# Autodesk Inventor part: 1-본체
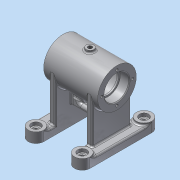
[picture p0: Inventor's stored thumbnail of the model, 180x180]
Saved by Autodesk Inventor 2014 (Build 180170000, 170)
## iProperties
Created: 2015-11
Part Number: 1-본체
Material: 알루미늄 6061
Document SubType Name: Modeling
Designer: 103-21
Mass: 358.521 g
Surface Area: 458.965 cm^2
Volume: 132.296 cm^3
Density: 2.71 g/cm^3
Appearance: 알루미늄 - 평지
Author: 103-21
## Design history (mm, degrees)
sketch "스케치1"
  geometry: L1 (40, -40)-(-40, -40); L2 (-40, -40)-(-40, 40); L3 (-40, 40)-(40, 40); L4 (40, 40)-(40, -40); L5 (40, -40)-(-40, 40); L6 (-40, -40)-(40, 40); L7 (-20, 40)-(-20, -40); L8 (20, 40)-(20, -40); 1 further point
  constraints: 16 end point, 4 point on line, 3 perpendicular, 2 midpoint, 2 parallel, 1 horizontal
  dimensions: "d0" = 20 distance of L7.start L2.end; "d1" = 20 distance of L3.end L8.start; "d2" = 80 distance of L1.end L2.end; "d3" = 80 distance between parallel lines of L4 L2
extrude "돌출1" new body sketch "스케치1" distance "d4" = 10; taper "d5" = 0 deg
sketch "스케치2"
  geometry: L1 (20, 40)-(40, 40) reference; L2 (40, -40)-(20, -40) reference; L3 (-40, -40)-(-40, 40) reference; L4 (-20, -40)-(-40, -40) reference; L5 (-20, 40)-(-20, -40) reference; L6 (-40, 40)-(-20, 40) reference; C1 r 10 at (30, 40); C2 r 10 at (-30, 40); C3 r 10 at (-30, -40); C4 r 10 at (30, -40); 1 further point
  constraints: 4 centre point, 4 midpoint, 3 equal radius
  dimensions: "d6" = 20 diameter of C3
extrude "돌출2" join sketch "스케치2" distance "d7" = 13; taper "d8" = 0 deg
node "작업 평면2"
sketch "스케치4"
  geometry: L1 (-35, 68)-(35, 68); L2 (-35, 84)-(-35, 93); L3 (-35, 93)-(35, 93); L4 (35, 93)-(35, 84); L5 (35, 84)-(23, 84); L6 (23, 84)-(23, 82); L7 (23, 82)-(21, 82); L8 (21, 82)-(21, 89); L9 (21, 89)-(-21, 89); L10 (-21, 89)-(-21, 82); L11 (-21, 82)-(-23, 82); L12 (-23, 82)-(-23, 84); L13 (-23, 84)-(-35, 84); L14 (-35, 84)-(-35, 68); L15 (35, 84)-(35, 68); 2 further points
  constraints: 30 end point, 10 parallel, 4 perpendicular, 2 point on line, 1 collinear, 1 horizontal, 1 midpoint, 1 vertical alignment
  dimensions: "d15" = 70 distance of L1.start L1.end; "d17" = 68 vertical distance of point (0, 0) L1.end; "d18" = 12 distance of L12.end L2.start; "d19" = 12 distance of L4.end L5.end; "d20" = 2 distance of L10.end L11.end; "d21" = 2 distance of L6.end L7.end; "d22" = 42 distance of L8.end L9.end (derived); "d23" = 28 diameter of L11 L1; "d24" = 32 diameter of L13 L1; "d25" = 42 diameter of L9 L1; "d26" = 32 diameter of L5 L1; "d27" = 50 diameter of L3 L1
revolve "회전1" stored, may be unused: angle "d28" = 90 deg
sketch "스케치5"
  geometry: L1 (0, 0)-(0, 80) reference; L2 (-68, 15)-(0, 15); L3 (-68, 65)-(0, 65); A1 r 25 centre (-68, 40) between (-68, 15) and (-68, 65) reference; 1 further point
  constraints: 4 end point, 2 perpendicular, 2 point on circle, 2 point on line, 2 tangent
extrude "돌출3" join sketch "스케치5" distance "d29" = 8; taper "d30" = 0 deg
node "작업 평면3"
node "작업 평면4"
sketch "스케치6" dims "d24" = 32
  geometry: L1 (20, 68)-(28, 68) reference; L2 (28, 68)-(28, 68) reference; L3 (20, 68)-(28, 68) reference; L4 (20, 68)-(20, 68) reference; L5 (-28, 68)-(-20, 68) reference; L6 (-20, 68)-(-20, 68) reference; L7 (-28, 68)-(-20, 68) reference; L8 (-28, 68)-(-28, 68) reference; L9 (-35, 43)-(-35, 93) reference; L10 (35, 43)-(35, 93) reference; L11 (-28, 10)-(-20, 10) reference; L12 (-28, 68)-(-28, 10) reference; L13 (-28, 68)-(-20, 68) reference; L14 (-20, 10)-(-20, 68) reference; L15 (20, 10)-(28, 10) reference; L16 (20, 10)-(20, 68) reference; L17 (20, 68)-(28, 68) reference; L18 (28, 68)-(28, 10) reference; L19 (-35, 43)-(35, 43) reference; L20 (-20, 23)-(20, 23); L21 (-8, 36.5)-(8, 36.5); L22 (8, 29.5)-(-8, 29.5); L23 (40, 0)-(20, 0) reference; L24 (-20, 23)-(-20, 51.226); L25 (20, 51.226)-(20, 23); L26 (20, 51.226)-(-20, 51.226); A1 r 3.5 centre (8, 33) between (8, 29.5) and (8, 36.5); A2 r 3.5 centre (-8, 33) between (-8, 36.5) and (-8, 29.5); 2 further points
  constraints: 12 end point, 4 point on circle, 4 point on line, 4 tangent, 2 centre point, 2 parallel, 2 perpendicular, 1 collinear, 1 midpoint, 1 vertical alignment
  dimensions: "d32" = 20 distance between parallel lines of L20 L19; "d33" = 23 dimension on A1 A2; "d34" = 3.5 radius of A2; "d35" = 33 distance from line of A1.centre L23; "d36" = 28.22614 distance of L20.start L24.end
extrude "돌출4" join sketch "스케치6" stored distance "d37" = 8; taper "d38" = 0 deg
sketch "스케치7"
  geometry: C1 r 10 at (0, 0) reference; C2 r 10 at (0, 80) reference; C3 r 10 at (60, 80) reference; C4 r 10 at (60, 0) reference; 5 further points
  constraints: 4 coincident
hole "구멍1" sketch "스케치7" at (0, 80), (60, 80), (60, 0), (0, 0) diameter "d39" = 6; stored, may be unused: countersink angle "d43" = 82 deg, drill point angle "d45" = 118 deg; dims "d40" = 6, "d41" = 12, "d42" = 4, "d44" = 8
node "작업 평면5"
sketch "스케치8"
  geometry: C1 r 5 at (0, 0); 1 further point
  constraints: 1 centre point, 1 coincident
  dimensions: "d47" = 10 diameter of C1
extrude "돌출5" join sketch "스케치8" stored distance "d48" = 8; taper "d49" = 0 deg
node "작업 평면6"
sketch "스케치9"
  geometry: L1 (0, 0)-(-24.249, -14); L2 (-24.249, -14)-(0, 0); L3 (0, 0)-(-25, 0); 1 further point
  constraints: 6 end point, 1 collinear, 1 horizontal, 1 horizontal alignment, 1 other
  dimensions: "d50" = 28 distance of L1.end L1.start; "d51" = 30 deg angle of L1 L3
node "작업 평면7"
sketch "스케치10"
  geometry: L1 (8, -12.286)-(-8, -12.286) reference; L2 (-20, 21.651)-(-20, -7.349) reference; C1 r 6 at (0, 0); 1 further point
  constraints: 1 centre point
  dimensions: "d52" = 12 diameter of C1; "d54" = 20 distance from line of L2 C1.centre; "d55" = 12.2859 distance from line of L1 C1.centre
extrude "돌출6" join sketch "스케치10" stored distance "d56" = 8; taper "d57" = 0 deg
revolve "회전2" stored, may be unused: angle "d58" = 90 deg
node "작업 평면8"
sketch "스케치11"
  geometry: L1 (35, 25)-(-35, 25) reference; L2 (-35, 25)-(-35, -25) reference; 4 further points
  constraints: 2 midpoint, 1 horizontal alignment, 1 vertical alignment, 1 other
feature "엠보싱1" sketch "스케치11" dims "d59" = 0.5, "d60" = 0
sketch "스케치12"
  geometry: C1 r 16 at (0, 0) reference; C2 r 25 at (0, 0) reference; A1 r 20 centre (0, 0) between (20, 0) and (-20, 0); 3 further points
  constraints: 4 point on circle, 2 horizontal alignment, 2 vertical alignment, 1 centre point, 1 coincident
  dimensions: "d61" = 40 diameter of A1
hole "구멍2" sketch "스케치12" at (20, 0), (-20, 0), (0, -20), (0, 20) diameter "d62" = 3.242; stored, may be unused: countersink angle "d66" = 82 deg, drill point angle "d68" = 118 deg; dims "d63" = 8, "d64" = 12, "d65" = 4, "d67" = 10
node "작업 평면9"
sketch "스케치13"
  geometry: C1 r 5 at (0, 0) reference; 1 further point
  constraints: 1 coincident
hole "구멍3" sketch "스케치13" at (0, 0) diameter "d69" = 5.188; stored, may be unused: countersink angle "d73" = 82 deg, drill point angle "d75" = 0 deg; dims "d70" = 8, "d71" = 12, "d72" = 4, "d74" = 10
sketch "스케치14"
  geometry: C1 r 6 at (0, 0) reference; 2 further points
  constraints: 1 coincident
hole "구멍4" sketch "스케치14" at (0, 0) diameter "d76" = 5.188; stored, may be unused: countersink angle "d80" = 82 deg, drill point angle "d82" = 0 deg; dims "d77" = 8, "d78" = 12, "d79" = 4, "d81" = 10
fillet "모깎기1" dims "d83" = 3, "d84" = 0.3, "d85" = 2, "d86" = 3.5
fillet "모깎기3" dims "d88" = 2
fillet "모깎기4" dims "d89" = 2
fillet "모깎기5" dims "d90" = 2
fillet "모깎기6" dims "d91" = 2
fillet "모깎기7" dims "d92" = 2
chamfer "모따기1" distance "d93" = 1; stored, may be unused: second distance "d94" = 2, angle "d95" = 45 deg
node "솔리드1"
mirror "대칭1"
mirror "대칭2"
node "투영된 루프1"
node "투영된 루프2"
node "투영된 루프3"
node "투영된 루프4"
node "투영된 루프5"
node "투영된 루프6"
node "투영된 루프7"
node "투영된 루프8"
other parameters: "d14" = 0, "d31" = 0, "d46" = -96
